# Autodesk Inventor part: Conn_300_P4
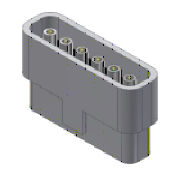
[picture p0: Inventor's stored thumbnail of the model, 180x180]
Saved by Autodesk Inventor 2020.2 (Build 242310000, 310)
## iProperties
Manager: www.cadconsulting.pl
Company: Fabian Stasiak CAD Consulting
Created: 2014-10
Part Number: Conn_300_P4
Material: Ogólny
Description: Wtyk typ 300, ALPHA
Document SubType Name: Modeling
Standard: ALPHA 100/2012
Designer: F.Stasiak
Manufacturer: ALPHA
Standards Organization: ISO
Language: pl-PL
Size Designation: Conn_300_P4
Categories: <MemberInstance><Categories><Category DisplayName="Kable i wiązki przewodów" InternalName="e4a7e005-5e42-4d16-b293-125e7f0d0512" Mnemonic="CABLEANDHARNESS"><Cat
Density: 1 g/cm^3
Appearance: Śnieg
Catalog Web Link: www.expertbooks.pl
IsCustomPart: 0
Author: F.Stasiak
Subject: Zbiór ćwiczeń. Autodesk Inventor 2020. Kurs Professional
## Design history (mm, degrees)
sketch "Szkic1"
  geometry: L1 (0, 0)-(30, 0); L2 (0, 2.5)-(20, 2.5); L3 (20, 2.5)-(20, -2.5); L4 (20, -2.5)-(0, -2.5); L5 (0, -2.5)-(0, 2.5); 7 further points
  constraints: 10 end point, 2 horizontal, 2 parallel, 1 coincident, 1 midpoint, 1 perpendicular
  dimensions: "d0" = 5 distance of point (7.5, 0) point (2.5, 0); "d1" = 5 distance of point (12.5, 0) point (7.5, 0) (= d0); "d2" = 5 distance of point (17.5, 0) point (12.5, 0) (= d0); "d3" = 5 distance of point (22.5, 0) point (17.5, 0) (= d0); "d4" = 5 distance of point (22.5, 0) point (27.5, 0) (= d0); "d16" = 2.5 distance of point (2.5, 0) L1.start; "d17" = 2.5 distance of point (27.5, 0) L1.end (= d16); "d18" = 5 distance of L4.end L2.start; "d19" = 20 distance of L3.end L4.end (= 0.5 x LPINÓW)
node "Oś konstrukcyjna1"
node "Oś konstrukcyjna2"
node "Oś konstrukcyjna3"
node "Oś konstrukcyjna4"
node "Oś konstrukcyjna5"
node "Oś konstrukcyjna6"
extrude "Wyciągnięcie proste3" new body sketch "Szkic1" distance "d20" = 3; taper "d21" = 0 deg
sketch "Szkic3"
  geometry: C1 r 1 at (2.5, 0); 2 further points
  constraints: 1 centre point, 1 coincident
  dimensions: "d22" = 2 diameter of C1
extrude "Wyciągnięcie proste4" join sketch "Szkic3" distance "d23" = 5; taper "d24" = 0 deg; dims "d29" = 15, "d30" = 0
sketch "Szkic4"
  geometry: C1 r 1.5 at (0, 0)
  constraints: 1 centre point
  dimensions: "d31" = 3 diameter of C1
extrude "Wyciągnięcie proste5" join sketch "Szkic4" stored distance "d32" = 0; taper "d33" = 0 deg
sketch "Szkic5"
  geometry: C1 r 0.9 at (0, 0)
  constraints: 1 centre point
  dimensions: "d34" = 1.8 diameter of C1
extrude "Wyciągnięcie proste6" cut sketch "Szkic5" distance "d35" = 7; taper "d36" = 0 deg
fillet "Zaokrąglenie3" dims "d45" = 1
pattern_linear "Szyk prostokątny2" dims "d27" = 5
node "Płaszczyzna konstrukcyjna1"
sketch "Szkic6"
  geometry: L1 (0, -2.5)-(20, -2.5) reference; L2 (20, -2.5)-(20, 2.5) reference; L3 (20, 2.5)-(0, 2.5) reference; L4 (0, 2.5)-(0, -2.5) reference; L5 (21.5, -4)-(-1.5, -4); L6 (-1.5, -4)-(-1.5, 4); L7 (-1.5, 4)-(21.5, 4); L8 (21.5, 4)-(21.5, -4)
  constraints: 8 end point, 3 other
  dimensions: "d37" = 1.5 distance between parallel lines of L5 L1
extrude "Wyciągnięcie proste7" join sketch "Szkic6" distance "d38" = 15.25; taper "d39" = 0 deg
fillet "Zaokrąglenie1" dims "d40" = 1
fillet "Zaokrąglenie2" dims "d41" = 2.5
chamfer "Faza1" distance "d42" = 1.05; stored, may be unused: second distance "d43" = 11, angle "d44" = 45 deg
sketch "Szkic7"
  geometry: L1 (-1.5, -1.5)-(-1.5, 1.5) reference; L2 (19, -4)-(1, -4) reference; L3 (21.5, 1.5)-(21.5, -1.5) reference; L4 (1, 4)-(19, 4) reference; L5 (-3, -1.5)-(-3, 1.5); L6 (1, 5.5)-(19, 5.5); L7 (23, 1.5)-(23, -1.5); L8 (19, -5.5)-(1, -5.5); C1 r 1.5 at (12.5, 0) reference; C2 r 1.5 at (7.5, 0) reference; C3 r 1.5 at (2.5, 0) reference; A1 r 2.5 centre (1, 1.5) between (1, 4) and (-1.5, 1.5) reference; A2 r 2.5 centre (1, -1.5) between (-1.5, -1.5) and (1, -4) reference; A3 r 2.5 centre (19, -1.5) between (19, -4) and (21.5, -1.5) reference; A4 r 2.5 centre (19, 1.5) between (21.5, 1.5) and (19, 4) reference; A5 r 4 centre (1, -1.5) between (-3, -1.5) and (1, -5.5); A6 r 4 centre (1, 1.5) between (1, 5.5) and (-3, 1.5); A7 r 4 centre (19, 1.5) between (23, 1.5) and (19, 5.5); A8 r 4 centre (19, -1.5) between (19, -5.5) and (23, -1.5)
  constraints: 8 end point, 8 point on circle, 4 centre point, 7 other
  dimensions: "d46" = 1.5 distance between parallel lines of L2 L8
extrude "Wyciągnięcie proste8" join sketch "Szkic7" stored distance "d47" = 12; taper "d48" = 0 deg
sketch "Szkic8"
  geometry: L1 (-1, 4)-(-19, 4) reference; L2 (1.5, -1.5)-(1.5, 1.5) reference; L3 (-19, -4)-(-1, -4) reference; L4 (-21.5, 1.5)-(-21.5, -1.5) reference; L5 (3, -1.5)-(3, 1.5) reference; L6 (-1, 5.5)-(-19, 5.5) reference; L7 (-23, 1.5)-(-23, -1.5) reference; L8 (-19, -5.5)-(-1, -5.5) reference; L9 (-7, -5.5)-(-13, -5.5); L10 (-13, -5.5)-(-13, -4); L11 (-13, -4)-(-7, -4); L12 (-7, -4)-(-7, -5.5); A1 r 2.5 centre (-1, 1.5) between (1.5, 1.5) and (-1, 4) reference; A2 r 2.5 centre (-1, -1.5) between (-1, -4) and (1.5, -1.5) reference; A3 r 2.5 centre (-19, -1.5) between (-21.5, -1.5) and (-19, -4) reference; A4 r 2.5 centre (-19, 1.5) between (-19, 4) and (-21.5, 1.5) reference; A5 r 4 centre (-1, -1.5) between (-1, -5.5) and (3, -1.5) reference; A6 r 4 centre (-1, 1.5) between (3, 1.5) and (-1, 5.5) reference; A7 r 4 centre (-19, 1.5) between (-19, 5.5) and (-23, 1.5) reference; A8 r 4 centre (-19, -1.5) between (-23, -1.5) and (-19, -5.5) reference; 2 further points
  constraints: 8 end point, 4 midpoint, 2 parallel, 1 horizontal, 1 perpendicular
  dimensions: "d49" = 6 distance of L9.start L9.end
extrude "Wyciągnięcie proste9" join sketch "Szkic8" distance "d50" = 6.5; taper "d51" = 0 deg
node "Punkt konstrukcyjny2"
node "Punkt konstrukcyjny3"
node "Punkt konstrukcyjny4"
node "Punkt konstrukcyjny5"
node "Punkt konstrukcyjny6"
node "Punkt konstrukcyjny7"
node "1"
node "2"
node "3"
node "4"
node "5"
node "6"
node "Bryła2"
node "Pętla rzutowana1"
node "Pętla rzutowana2"
other parameters: "d28" = 8
